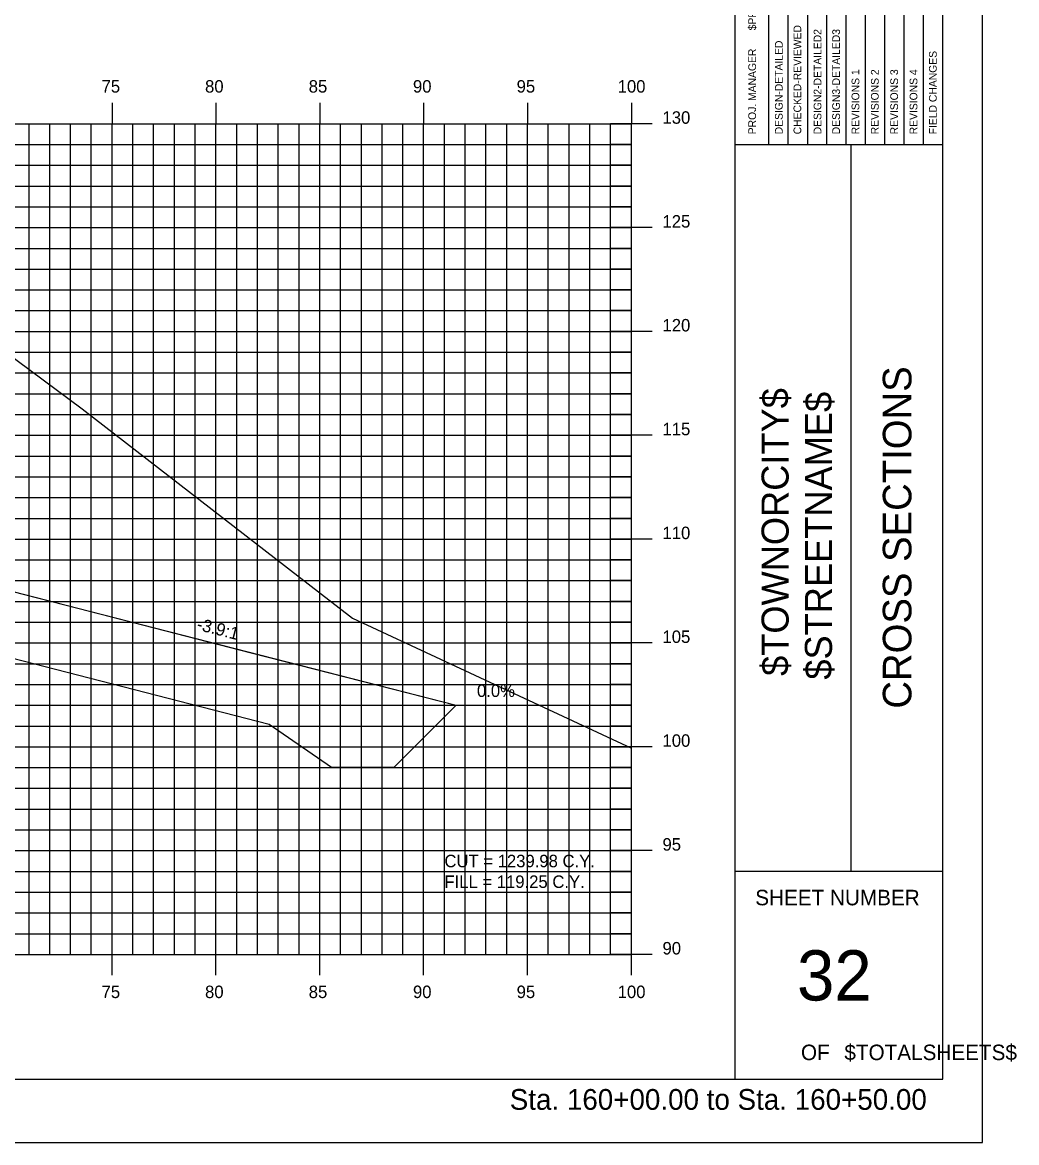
# Model space of a CAD drawing. Extents: x 850598 to 870284, y 366541 to 366651.
# Drawn here: x 853604.4 to 853652.3, y 366541.2 to 366595.1 of the extents above; entities that cross this region are included whole.
import ezdxf

# ---------------------------------------------------------------- set-up
doc = ezdxf.new("R2010")
doc.units = 0
for name, color, linetype in [('ANNOTATION', 7, 'Continuous'), ('BORDER', 7, 'Continuous'), ('D_Drainage_RipRap', 7, 'Continuous'), ('D_Roadway_Centerline', 7, 'Continuous'), ('D_Roadway_SlopeLines', 7, 'Continuous'), ('D_Text_Standard', 7, 'Continuous'), ('H_V ANNOTATION', 7, 'Continuous'), ('HIGHWAY_TITLE', 7, 'Continuous'), ('MAJOR', 7, 'Continuous'), ('MINOR', 7, 'Continuous'), ('PLOT BOUNDARY', 7, 'Continuous'), ('S_Roadway_Centerline', 7, 'Continuous')]:
    doc.layers.add(name, color=color, linetype=linetype)

msp = doc.modelspace()

# ---------------------------------------------------------------- linework, layer by layer
at = {"layer": 'BORDER'}
for p, q in [((853638.732, 366544.225), (853638.732, 366649.225)), ((853648.732, 366544.225), (853648.732, 366649.225)), ((853638.732, 366589.228), (853648.732, 366589.228)), ((853644.323, 366554.228), (853644.323, 366589.228)), ((853638.732, 366554.228), (853648.732, 366554.228)), ((853488.732, 366544.225), (853648.732, 366544.225))]:
    msp.add_line(p, q, dxfattribs=at)
for points in [[(853641.28, 366589.231), (853641.28, 366606.728)], [(853642.211, 366606.728), (853642.211, 366589.231)], [(853643.143, 366589.231), (853643.143, 366606.728)], [(853644.075, 366589.231), (853644.075, 366606.728)], [(853645.006, 366589.231), (853645.006, 366606.728)], [(853645.938, 366589.231), (853645.938, 366606.728)], [(853646.87, 366589.231), (853646.87, 366606.728)], [(853647.801, 366589.231), (853647.801, 366606.728)], [(853640.348, 366589.231), (853640.348, 366606.022)]]:
    msp.add_lwpolyline(points, dxfattribs=at)
at = {"layer": 'D_Drainage_RipRap'}
msp.add_lwpolyline([(853601.891, 366568.225), (853615.432, 366564.754), (853625.294, 366562.225), (853622.294, 366559.225), (853619.294, 366559.225), (853616.294, 366561.304), (853602.753, 366564.775), (853601.891, 366566.725), (853556.732, 366578.303), (853556.732, 366579.803)], close=True, dxfattribs=at)
at = {"layer": 'D_Roadway_Centerline'}
msp.add_lwpolyline([(853500.815, 366575.951), (853508.732, 366578.59), (853512.534, 366579.857), (853518.732, 366581.923), (853522.732, 366582.163), (853533.732, 366582.493), (853544.732, 366582.163), (853548.732, 366581.923), (853550.732, 366581.803), (853556.732, 366579.803), (853601.891, 366568.225), (853615.432, 366564.754), (853625.294, 366562.225), (853629.294, 366562.225)], dxfattribs=at)
at = {"layer": 'D_Roadway_SlopeLines'}
msp.add_lwpolyline([(853556.732, 366579.803), (853625.294, 366562.225), (853625.294, 366562.225)], dxfattribs=at)
at = {"layer": 'MAJOR'}
for p, q in [((853608.732, 366591.227), (853608.732, 366590.225)), ((853608.732, 366591.227), (853608.732, 366590.225)), ((853613.732, 366591.227), (853613.732, 366590.225)), ((853613.732, 366591.227), (853613.732, 366590.225)), ((853618.732, 366591.227), (853618.732, 366590.225)), ((853618.732, 366591.227), (853618.732, 366590.225)), ((853623.732, 366591.227), (853623.732, 366590.225)), ((853623.732, 366591.227), (853623.732, 366590.225)), ((853628.732, 366591.227), (853628.732, 366590.225)), ((853628.732, 366591.227), (853628.732, 366590.225)), ((853633.732, 366591.227), (853633.732, 366590.225)), ((853633.732, 366591.227), (853633.732, 366590.225)), ((853493.732, 366590.225), (853633.732, 366590.225)), ((853493.732, 366590.225), (853633.732, 366590.225)), ((853493.732, 366590.225), (853633.732, 366590.225)), ((853493.732, 366590.225), (853633.732, 366590.225)), ((853608.732, 366550.225), (853608.732, 366590.225)), ((853608.732, 366550.225), (853608.732, 366590.225)), ((853613.732, 366550.225), (853613.732, 366590.225)), ((853613.732, 366550.225), (853613.732, 366590.225)), ((853618.732, 366550.225), (853618.732, 366590.225)), ((853618.732, 366550.225), (853618.732, 366590.225)), ((853623.732, 366550.225), (853623.732, 366590.225)), ((853623.732, 366550.225), (853623.732, 366590.225)), ((853628.732, 366550.225), (853628.732, 366590.225)), ((853628.732, 366550.225), (853628.732, 366590.225)), ((853634.734, 366590.225), (853632.73, 366590.225)), ((853634.734, 366590.225), (853632.73, 366590.225)), ((853633.732, 366550.225), (853633.732, 366590.225)), ((853633.732, 366550.225), (853633.732, 366590.225)), ((853633.732, 366550.225), (853633.732, 366590.225)), ((853633.732, 366550.225), (853633.732, 366590.225)), ((853493.732, 366585.225), (853633.732, 366585.225)), ((853493.732, 366585.225), (853633.732, 366585.225)), ((853634.734, 366585.225), (853632.73, 366585.225)), ((853634.734, 366585.225), (853632.73, 366585.225)), ((853493.732, 366580.225), (853633.732, 366580.225)), ((853493.732, 366580.225), (853633.732, 366580.225)), ((853634.734, 366580.225), (853632.73, 366580.225)), ((853634.734, 366580.225), (853632.73, 366580.225)), ((853493.732, 366575.225), (853633.732, 366575.225)), ((853493.732, 366575.225), (853633.732, 366575.225)), ((853634.734, 366575.225), (853632.73, 366575.225)), ((853634.734, 366575.225), (853632.73, 366575.225)), ((853493.732, 366570.225), (853633.732, 366570.225)), ((853493.732, 366570.225), (853633.732, 366570.225)), ((853634.734, 366570.225), (853632.73, 366570.225)), ((853634.734, 366570.225), (853632.73, 366570.225)), ((853493.732, 366565.225), (853633.732, 366565.225)), ((853493.732, 366565.225), (853633.732, 366565.225)), ((853634.734, 366565.225), (853632.73, 366565.225)), ((853634.734, 366565.225), (853632.73, 366565.225)), ((853493.732, 366560.225), (853633.732, 366560.225)), ((853493.732, 366560.225), (853633.732, 366560.225)), ((853634.734, 366560.225), (853632.73, 366560.225)), ((853634.734, 366560.225), (853632.73, 366560.225)), ((853493.732, 366555.225), (853633.732, 366555.225)), ((853493.732, 366555.225), (853633.732, 366555.225)), ((853634.734, 366555.225), (853632.73, 366555.225)), ((853634.734, 366555.225), (853632.73, 366555.225)), ((853493.732, 366550.225), (853633.732, 366550.225)), ((853493.732, 366550.225), (853633.732, 366550.225)), ((853493.732, 366550.225), (853633.732, 366550.225)), ((853493.732, 366550.225), (853633.732, 366550.225)), ((853608.732, 366549.223), (853608.732, 366550.225)), ((853608.732, 366549.223), (853608.732, 366550.225)), ((853613.732, 366549.223), (853613.732, 366550.225)), ((853613.732, 366549.223), (853613.732, 366550.225)), ((853618.732, 366549.223), (853618.732, 366550.225)), ((853618.732, 366549.223), (853618.732, 366550.225)), ((853623.732, 366549.223), (853623.732, 366550.225)), ((853623.732, 366549.223), (853623.732, 366550.225)), ((853628.732, 366549.223), (853628.732, 366550.225)), ((853628.732, 366549.223), (853628.732, 366550.225)), ((853634.734, 366550.225), (853632.73, 366550.225)), ((853634.734, 366550.225), (853632.73, 366550.225)), ((853633.732, 366549.223), (853633.732, 366550.225)), ((853633.732, 366549.223), (853633.732, 366550.225))]:
    msp.add_line(p, q, dxfattribs=at)
at = {"layer": 'MINOR'}
for p, q in [((853604.732, 366550.225), (853604.732, 366590.225)), ((853604.732, 366550.225), (853604.732, 366590.225)), ((853605.732, 366550.225), (853605.732, 366590.225)), ((853605.732, 366550.225), (853605.732, 366590.225)), ((853606.732, 366550.225), (853606.732, 366590.225)), ((853606.732, 366550.225), (853606.732, 366590.225)), ((853607.732, 366550.225), (853607.732, 366590.225)), ((853607.732, 366550.225), (853607.732, 366590.225)), ((853609.732, 366550.225), (853609.732, 366590.225)), ((853609.732, 366550.225), (853609.732, 366590.225)), ((853610.732, 366550.225), (853610.732, 366590.225)), ((853610.732, 366550.225), (853610.732, 366590.225)), ((853611.732, 366550.225), (853611.732, 366590.225)), ((853611.732, 366550.225), (853611.732, 366590.225)), ((853612.732, 366550.225), (853612.732, 366590.225)), ((853612.732, 366550.225), (853612.732, 366590.225)), ((853614.732, 366550.225), (853614.732, 366590.225)), ((853614.732, 366550.225), (853614.732, 366590.225)), ((853615.732, 366550.225), (853615.732, 366590.225)), ((853615.732, 366550.225), (853615.732, 366590.225)), ((853616.732, 366550.225), (853616.732, 366590.225)), ((853616.732, 366550.225), (853616.732, 366590.225)), ((853617.732, 366550.225), (853617.732, 366590.225)), ((853617.732, 366550.225), (853617.732, 366590.225)), ((853619.732, 366550.225), (853619.732, 366590.225)), ((853619.732, 366550.225), (853619.732, 366590.225)), ((853620.732, 366550.225), (853620.732, 366590.225)), ((853620.732, 366550.225), (853620.732, 366590.225)), ((853621.732, 366550.225), (853621.732, 366590.225)), ((853621.732, 366550.225), (853621.732, 366590.225)), ((853622.732, 366550.225), (853622.732, 366590.225)), ((853622.732, 366550.225), (853622.732, 366590.225)), ((853624.732, 366550.225), (853624.732, 366590.225)), ((853624.732, 366550.225), (853624.732, 366590.225)), ((853625.732, 366550.225), (853625.732, 366590.225)), ((853625.732, 366550.225), (853625.732, 366590.225)), ((853626.732, 366550.225), (853626.732, 366590.225)), ((853626.732, 366550.225), (853626.732, 366590.225)), ((853627.732, 366550.225), (853627.732, 366590.225)), ((853627.732, 366550.225), (853627.732, 366590.225)), ((853629.732, 366550.225), (853629.732, 366590.225)), ((853629.732, 366550.225), (853629.732, 366590.225)), ((853630.732, 366550.225), (853630.732, 366590.225)), ((853630.732, 366550.225), (853630.732, 366590.225)), ((853631.732, 366550.225), (853631.732, 366590.225)), ((853631.732, 366550.225), (853631.732, 366590.225)), ((853632.732, 366550.225), (853632.732, 366590.225)), ((853632.732, 366550.225), (853632.732, 366590.225)), ((853493.732, 366589.225), (853633.732, 366589.225)), ((853493.732, 366589.225), (853633.732, 366589.225)), ((853633.732, 366589.225), (853632.73, 366589.225)), ((853633.732, 366589.225), (853632.73, 366589.225)), ((853493.732, 366588.225), (853633.732, 366588.225)), ((853493.732, 366588.225), (853633.732, 366588.225)), ((853633.732, 366588.225), (853632.73, 366588.225)), ((853633.732, 366588.225), (853632.73, 366588.225)), ((853493.732, 366587.225), (853633.732, 366587.225)), ((853493.732, 366587.225), (853633.732, 366587.225)), ((853633.732, 366587.225), (853632.73, 366587.225)), ((853633.732, 366587.225), (853632.73, 366587.225)), ((853493.732, 366586.225), (853633.732, 366586.225)), ((853493.732, 366586.225), (853633.732, 366586.225)), ((853633.732, 366586.225), (853632.73, 366586.225)), ((853633.732, 366586.225), (853632.73, 366586.225)), ((853493.732, 366584.225), (853633.732, 366584.225)), ((853493.732, 366584.225), (853633.732, 366584.225)), ((853633.732, 366584.225), (853632.73, 366584.225)), ((853633.732, 366584.225), (853632.73, 366584.225)), ((853493.732, 366583.225), (853633.732, 366583.225)), ((853493.732, 366583.225), (853633.732, 366583.225)), ((853633.732, 366583.225), (853632.73, 366583.225)), ((853633.732, 366583.225), (853632.73, 366583.225)), ((853493.732, 366582.225), (853633.732, 366582.225)), ((853493.732, 366582.225), (853633.732, 366582.225)), ((853633.732, 366582.225), (853632.73, 366582.225)), ((853633.732, 366582.225), (853632.73, 366582.225)), ((853493.732, 366581.225), (853633.732, 366581.225)), ((853493.732, 366581.225), (853633.732, 366581.225)), ((853633.732, 366581.225), (853632.73, 366581.225)), ((853633.732, 366581.225), (853632.73, 366581.225)), ((853493.732, 366579.225), (853633.732, 366579.225)), ((853493.732, 366579.225), (853633.732, 366579.225)), ((853633.732, 366579.225), (853632.73, 366579.225)), ((853633.732, 366579.225), (853632.73, 366579.225)), ((853493.732, 366578.225), (853633.732, 366578.225)), ((853493.732, 366578.225), (853633.732, 366578.225)), ((853633.732, 366578.225), (853632.73, 366578.225)), ((853633.732, 366578.225), (853632.73, 366578.225)), ((853493.732, 366577.225), (853633.732, 366577.225)), ((853493.732, 366577.225), (853633.732, 366577.225)), ((853633.732, 366577.225), (853632.73, 366577.225)), ((853633.732, 366577.225), (853632.73, 366577.225)), ((853493.732, 366576.225), (853633.732, 366576.225)), ((853493.732, 366576.225), (853633.732, 366576.225)), ((853633.732, 366576.225), (853632.73, 366576.225)), ((853633.732, 366576.225), (853632.73, 366576.225)), ((853493.732, 366574.225), (853633.732, 366574.225)), ((853493.732, 366574.225), (853633.732, 366574.225)), ((853633.732, 366574.225), (853632.73, 366574.225)), ((853633.732, 366574.225), (853632.73, 366574.225)), ((853493.732, 366573.225), (853633.732, 366573.225)), ((853493.732, 366573.225), (853633.732, 366573.225)), ((853633.732, 366573.225), (853632.73, 366573.225)), ((853633.732, 366573.225), (853632.73, 366573.225)), ((853493.732, 366572.225), (853633.732, 366572.225)), ((853493.732, 366572.225), (853633.732, 366572.225)), ((853633.732, 366572.225), (853632.73, 366572.225)), ((853633.732, 366572.225), (853632.73, 366572.225)), ((853493.732, 366571.225), (853633.732, 366571.225)), ((853493.732, 366571.225), (853633.732, 366571.225)), ((853633.732, 366571.225), (853632.73, 366571.225)), ((853633.732, 366571.225), (853632.73, 366571.225)), ((853493.732, 366569.225), (853633.732, 366569.225)), ((853493.732, 366569.225), (853633.732, 366569.225)), ((853633.732, 366569.225), (853632.73, 366569.225)), ((853633.732, 366569.225), (853632.73, 366569.225)), ((853493.732, 366568.225), (853633.732, 366568.225)), ((853493.732, 366568.225), (853633.732, 366568.225)), ((853633.732, 366568.225), (853632.73, 366568.225)), ((853633.732, 366568.225), (853632.73, 366568.225)), ((853493.732, 366567.225), (853633.732, 366567.225)), ((853493.732, 366567.225), (853633.732, 366567.225)), ((853633.732, 366567.225), (853632.73, 366567.225)), ((853633.732, 366567.225), (853632.73, 366567.225)), ((853493.732, 366566.225), (853633.732, 366566.225)), ((853493.732, 366566.225), (853633.732, 366566.225)), ((853633.732, 366566.225), (853632.73, 366566.225)), ((853633.732, 366566.225), (853632.73, 366566.225)), ((853493.732, 366564.225), (853633.732, 366564.225)), ((853493.732, 366564.225), (853633.732, 366564.225)), ((853633.732, 366564.225), (853632.73, 366564.225)), ((853633.732, 366564.225), (853632.73, 366564.225)), ((853493.732, 366563.225), (853633.732, 366563.225)), ((853493.732, 366563.225), (853633.732, 366563.225)), ((853633.732, 366563.225), (853632.73, 366563.225)), ((853633.732, 366563.225), (853632.73, 366563.225)), ((853493.732, 366562.225), (853633.732, 366562.225)), ((853493.732, 366562.225), (853633.732, 366562.225)), ((853633.732, 366562.225), (853632.73, 366562.225)), ((853633.732, 366562.225), (853632.73, 366562.225)), ((853493.732, 366561.225), (853633.732, 366561.225)), ((853493.732, 366561.225), (853633.732, 366561.225)), ((853633.732, 366561.225), (853632.73, 366561.225)), ((853633.732, 366561.225), (853632.73, 366561.225)), ((853493.732, 366559.225), (853633.732, 366559.225)), ((853493.732, 366559.225), (853633.732, 366559.225)), ((853633.732, 366559.225), (853632.73, 366559.225)), ((853633.732, 366559.225), (853632.73, 366559.225)), ((853493.732, 366558.225), (853633.732, 366558.225)), ((853493.732, 366558.225), (853633.732, 366558.225)), ((853633.732, 366558.225), (853632.73, 366558.225)), ((853633.732, 366558.225), (853632.73, 366558.225)), ((853493.732, 366557.225), (853633.732, 366557.225)), ((853493.732, 366557.225), (853633.732, 366557.225)), ((853633.732, 366557.225), (853632.73, 366557.225)), ((853633.732, 366557.225), (853632.73, 366557.225)), ((853493.732, 366556.225), (853633.732, 366556.225)), ((853493.732, 366556.225), (853633.732, 366556.225)), ((853633.732, 366556.225), (853632.73, 366556.225)), ((853633.732, 366556.225), (853632.73, 366556.225)), ((853493.732, 366554.225), (853633.732, 366554.225)), ((853493.732, 366554.225), (853633.732, 366554.225)), ((853633.732, 366554.225), (853632.73, 366554.225)), ((853633.732, 366554.225), (853632.73, 366554.225)), ((853493.732, 366553.225), (853633.732, 366553.225)), ((853493.732, 366553.225), (853633.732, 366553.225)), ((853633.732, 366553.225), (853632.73, 366553.225)), ((853633.732, 366553.225), (853632.73, 366553.225)), ((853493.732, 366552.225), (853633.732, 366552.225)), ((853493.732, 366552.225), (853633.732, 366552.225)), ((853633.732, 366552.225), (853632.73, 366552.225)), ((853633.732, 366552.225), (853632.73, 366552.225)), ((853493.732, 366551.225), (853633.732, 366551.225)), ((853493.732, 366551.225), (853633.732, 366551.225)), ((853633.732, 366551.225), (853632.73, 366551.225)), ((853633.732, 366551.225), (853632.73, 366551.225))]:
    msp.add_line(p, q, dxfattribs=at)
at = {"layer": 'PLOT BOUNDARY'}
msp.add_lwpolyline([(853480.639, 366541.166), (853650.639, 366541.166), (853650.639, 366651.166), (853480.639, 366651.166)], close=True, dxfattribs=at)
at = {"layer": 'S_Roadway_Centerline'}
msp.add_lwpolyline([(853541.187, 366578.126), (853559.005, 366580.26), (853560.1, 366580.346), (853560.792, 366580.477), (853561.629, 366580.694), (853563.901, 366581.111), (853564.893, 366581.35), (853565.786, 366581.438), (853566.121, 366581.44), (853566.24, 366581.429), (853568.109, 366581.512), (853570.913, 366581.614), (853580.971, 366582.046), (853592.187, 366581.691), (853597.183, 366581.561), (853598.997, 366581.045), (853602.27, 366580.226), (853607.292, 366576.5), (853620.309, 366566.422), (853633.732, 366560.153)], dxfattribs=at)

# ---------------------------------------------------------------- texts
at = {"layer": 'ANNOTATION'}
msp.add_text('-3.9:1', height=0.6, rotation=345.6204, dxfattribs=at).set_placement((853612.767, 366565.869))
msp.add_text('0.0%', height=0.6, dxfattribs=at).set_placement((853626.299, 366562.625))
at = {"layer": 'BORDER'}
for s, height, rotation, p in [('$PROJMANAGER$', 0.37275, 90, (853639.736, 366594.723)), ('CHECKED-REVIEWED', 0.37275, 90, (853641.913, 366589.716)), ('DESIGN2-DETAILED2', 0.37275, 90, (853642.882, 366589.716)), ('DESIGN3-DETAILED3', 0.37275, 90, (853643.777, 366589.716)), ('PROJ. MANAGER', 0.37275, 90, (853639.736, 366589.716)), ('DESIGN-DETAILED', 0.37275, 90, (853641.019, 366589.716)), ('FIELD CHANGES', 0.37275, 90, (853648.435, 366589.716)), ('REVISIONS 1', 0.37275, 90, (853644.708, 366589.716)), ('REVISIONS 2', 0.37275, 90, (853645.64, 366589.716)), ('REVISIONS 3', 0.37275, 90, (853646.572, 366589.716)), ('REVISIONS 4', 0.37275, 90, (853647.503, 366589.716)), ('CROSS SECTIONS', 1.37787, 90, (853647.217, 366562.062)), ('SHEET NUMBER', 0.74527, 360, (853639.698, 366552.592)), ('32', 2.4194, 360, (853641.708, 366548.008)), ('OF', 0.7453, 360, (853641.899, 366545.138)), ('$TOTALSHEETS$', 0.74527, 360, (853643.989, 366545.138))]:
    msp.add_text(s, height=height, rotation=rotation, dxfattribs=at).set_placement(p)
at = {"layer": 'D_Text_Standard'}
for s, p in [('CUT = 1239.98 C.Y.', (853624.732, 366554.425)), ('FILL = 119.25 C.Y.', (853624.732, 366553.429))]:
    msp.add_text(s, height=0.6, dxfattribs=at).set_placement(p)
at = {"layer": 'H_V ANNOTATION'}
for s, height, p in [('75', 0.6, (853608.226, 366591.725)), ('80', 0.6, (853613.207, 366591.725)), ('85', 0.6, (853618.199, 366591.725)), ('90', 0.6, (853623.218, 366591.725)), ('95', 0.6, (853628.21, 366591.725)), ('100', 0.6, (853633.074, 366591.725)), ('130', 0.6, (853635.232, 366590.225)), ('125', 0.6, (853635.232, 366585.225)), ('120', 0.6, (853635.232, 366580.225)), ('115', 0.6, (853635.232, 366575.225)), ('110', 0.6, (853635.232, 366570.225)), ('105', 0.6, (853635.232, 366565.225)), ('100', 0.6, (853635.232, 366560.225)), ('95', 0.6, (853635.232, 366555.225)), ('90', 0.6, (853635.232, 366550.225)), ('75', 0.6, (853608.226, 366548.125)), ('80', 0.6, (853613.207, 366548.125)), ('85', 0.6, (853618.199, 366548.125)), ('90', 0.6, (853623.218, 366548.125)), ('95', 0.6, (853628.21, 366548.125)), ('100', 0.6, (853633.074, 366548.125)), ('Sta. 160+00.00 to Sta. 160+50.00', 1.0002, (853627.878, 366542.745))]:
    msp.add_text(s, height=height, dxfattribs=at).set_placement(p)
at = {"layer": 'HIGHWAY_TITLE'}
for s, p in [('$TOWNORCITY$', (853641.305, 366563.637)), ('$STREETNAME$', (853643.392, 366563.457))]:
    msp.add_text(s, height=1.30428, rotation=90, dxfattribs=at).set_placement(p)

doc.saveas('drawing.dxf')
